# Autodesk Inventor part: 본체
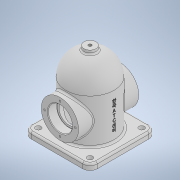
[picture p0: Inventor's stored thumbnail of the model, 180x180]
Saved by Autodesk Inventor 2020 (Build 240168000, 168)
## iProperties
Created: 2021-07
Part Number: 본체
Material: 일반
Document SubType Name: Modeling
Designer: Owner
Density: 1 g/cm^3
Appearance: 기본값
Mass: 320.706 g
Surface Area: 800.755 cm^2
Volume: 320.706 cm^3
Author: Owner
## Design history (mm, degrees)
sketch "스케치2"
  geometry: C1 r 40 at (0, 0); 1 further point
  constraints: 1 centre point, 1 coincident
  dimensions: "d0" = 80 diameter of C1
extrude "돌출1" new body sketch "스케치2" distance "d1" = 124; taper "d2" = 0 deg
fillet "모깎기1" dims "d3" = 40
feature "쉘1" dims "d4" = 8
node "작업 평면1"
sketch "스케치3"
  geometry: C1 r 31 at (0, 48); 1 further point
  constraints: 1 centre point, 1 vertical alignment
  dimensions: "d6" = 62 diameter of C1; "d7" = 48 distance of point (0, 0) C1.centre
extrude "돌출2" join sketch "스케치3" stored distance "d8" = 124; taper "d9" = 0 deg
sketch "스케치4"
  geometry: C1 r 31 at (0, 0) reference; 2 further points
  constraints: 1 coincident
hole "구멍1" sketch "스케치4" at (0, 0) diameter "d10" = 33; stored, may be unused: countersink angle "d14" = 90 deg, drill point angle "d16" = 0 deg; dims "d11" = 6, "d12" = 40, "d13" = 15, "d15" = 8
sketch "스케치5"
  geometry: C1 r 16.5 at (0, 48) reference; 2 further points
  constraints: 1 vertical alignment
  dimensions: "d17" = 25.5 distance of C1.centre point (0, 73.5)
hole "구멍2" sketch "스케치5" at (0, 73.5) diameter "d18" = 3.242; stored, may be unused: countersink angle "d22" = 90 deg, drill point angle "d24" = 118 deg; dims "d19" = 8, "d20" = 40, "d21" = 15, "d23" = 10
fillet "모깎기2" dims "d28" = 0.3
node "작업 평면2"
sketch "스케치6"
  geometry: C1 r 10 at (0, 0); 1 further point
  constraints: 1 centre point, 1 coincident
  dimensions: "d30" = 20 diameter of C1
extrude "돌출3" join sketch "스케치6" stored distance "d31" = 124; taper "d32" = 0 deg
sketch "스케치7"
  geometry: C1 r 10 at (0, 0) reference; 2 further points
  constraints: 1 coincident
hole "구멍3" sketch "스케치7" at (0, 0) diameter "d33" = 5.1881; stored, may be unused: countersink angle "d37" = 90 deg, drill point angle "d39" = 118 deg; dims "d34" = 30, "d35" = 40, "d36" = 15, "d38" = 16
sketch "스케치8"
  geometry: L1 (-55, -55)-(55, -55); L2 (55, -55)-(55, 55); L3 (55, 55)-(-55, 55); L4 (-55, 55)-(-55, -55); L5 (-55, -55)-(55, 55); L6 (55, -55)-(-55, 55); C1 r 2.594 at (0, 0) reference; C2 r 40 at (0, 0) reference; 1 further point
  constraints: 12 end point, 2 midpoint, 2 parallel, 1 horizontal, 1 perpendicular
  dimensions: "d40" = 110 distance of L3.end L2.end; "d41" = 110 distance of L2.end L1.end
extrude "돌출4" join sketch "스케치8" distance "d42" = 10; taper "d43" = 0 deg
fillet "모깎기3" dims "d44" = 12
fillet "모깎기4" dims "d45" = 3
sketch "스케치9"
  geometry: A1 r 9 centre (43, -43) between (43, -52) and (52, -43) reference; 2 further points
  constraints: 1 coincident
hole "구멍4" sketch "스케치9" at (43, -43) diameter "d46" = 9; stored, may be unused: countersink angle "d50" = 90 deg, drill point angle "d52" = 118 deg; dims "d47" = 30, "d48" = 40, "d49" = 15, "d51" = 16
node "작업 평면3"
sketch "스케치10"
  geometry: L1 (0, -43)-(0, 43) reference; L2 (71.992, 3.474)-(71.992, -3.474); L3 (71.992, -3.474)-(24.008, -3.474); L4 (24.008, -3.474)-(24.008, 3.474); L5 (24.008, 3.474)-(71.992, 3.474); 2 further points
  constraints: 1 midpoint, 2 other
feature "엠보싱1" sketch "스케치10" dims "d55" = 0.5, "d56" = 0
chamfer "모따기1" distance "d57" = 1; stored, may be unused: second distance "d58" = 2, angle "d59" = 45 deg
node "솔리드1"
pattern_circular "원형 패턴1" dims angle "d26" = 360 deg
mirror "미러1"
mirror "미러2"
mirror "미러3"
feature "A9D066F2-1C7D-4E18-AEED-F7BC21143FA4" dims "d10" = 33, "d11" = 6, "d12" = 40, "d13" = 15, "d14" = 90 deg, "d15" = 8, "d16" = 0
other parameters: "d29" = 129
